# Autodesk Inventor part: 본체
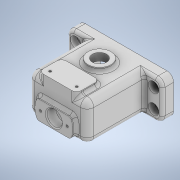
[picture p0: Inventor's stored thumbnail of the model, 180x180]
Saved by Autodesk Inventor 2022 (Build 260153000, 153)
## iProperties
Created: 2023-12
Part Number: 본체
Material: 일반
Document SubType Name: Modeling
Designer: PC-01
Density: 1 g/cm^3
Appearance: 기본값
Author: PC-01
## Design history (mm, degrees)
sketch "스케치1"
  geometry: L1 (-70, 0)-(70, 0) reference; L2 (0, -33.6)-(0, 33.6) reference; L3 (-50, 24)-(50, 24); L4 (50, 24)-(50, -24); L5 (50, -24)-(-50, -24); L6 (-50, -24)-(-50, 24); 1 further point
  constraints: 8 end point, 2 perpendicular, 1 horizontal, 2 other
  dimensions: "d0" = 100 distance of L3.start L3.end; "d1" = 48 distance of L3.end L4.end
extrude "돌출1" new body sketch "스케치1" stored distance "d2" = 76; taper "d3" = 0 deg
sketch "스케치2"
  geometry: L1 (50, -38)-(50, 38) reference; L2 (50, -26)-(31, -26); L3 (31, -26)-(31, 38); L4 (-50, 38)-(50, 38) reference; L5 (-31, 38)-(-31, -26); L6 (-31, -26)-(-50, -26); L7 (-50, -38)-(-50, 38) reference; L8 (31, 38)-(-31, 38); L9 (0, -53.2)-(0, 53.2) reference; L10 (70, 0)-(-70, 0) reference; L11 (50, -38)-(-50, -38) reference; L12 (50, -26)-(50, -38); L13 (50, -38)-(-50, -38); L14 (-50, -38)-(-50, -26); L15 (50, 38)-(50, -26); L16 (50, 38)-(31, 38); L17 (-31, 38)-(-50, 38); L18 (-50, 38)-(-50, -26); 2 further points
  constraints: 24 end point, 5 collinear, 5 perpendicular, 5 point on line, 1 vertical, 2 other
  dimensions: "d4" = 62 distance between parallel lines of L5 L3; "d5" = 12 distance between parallel lines of L11 L2
extrude "돌출2" cut sketch "스케치2" stored distance "d6" = 76; taper "d7" = 0 deg
sketch "스케치3"
  geometry: L1 (64, 0)-(0, 0) reference; L2 (76, 0)-(64, 0) reference; L3 (0, 0)-(76, 0); L4 (76, 0)-(76, 4); L5 (76, 48)-(76, 0) reference; L6 (0, 0)-(0, 48) reference; L7 (0, 0)-(0, 4); L8 (76, 4)-(0, 4); L9 (0, 48)-(64, 48) reference; L10 (0, 48)-(76, 48); L11 (76, 48)-(76, 44); L12 (76, 44)-(0, 44); L13 (0, 44)-(0, 48); 4 further points
  constraints: 16 end point, 3 point on line, 2 parallel, 2 perpendicular, 1 collinear, 1 horizontal
  dimensions: "d8" = 4 distance between parallel lines of L1 L8; "d9" = 4 distance between parallel lines of L9 L12
extrude "돌출3" cut sketch "스케치3" stored distance "d10" = 500; taper "d11" = 0 deg
sketch "스케치4"
  geometry: L1 (19, -12)-(-81, -12) reference; L2 (19, 0)-(19, -12) reference; C1 r 20 at (-31, 16); 1 further point
  constraints: 1 centre point
  dimensions: "d12" = 40 diameter of C1; "d13" = 28 distance from line of L1 C1.centre; "d14" = 50 distance from line of L2 C1.centre
extrude "돌출4" join sketch "스케치4" distance "d15" = 4; taper "d16" = 0 deg
sketch "스케치5"
  geometry: L1 (64, 0)-(0, 0) reference; L2 (64, 40)-(0, 40) reference; L3 (0, 0)-(4, 0); L4 (4, 0)-(4, 40); L5 (4, 40)-(0, 40); L6 (0, 40)-(0, 0); 3 further points
  constraints: 8 end point, 2 parallel, 1 horizontal, 1 perpendicular, 1 point on line
  dimensions: "d17" = 4 distance between parallel lines of L6 L4
extrude "돌출5" cut sketch "스케치5" stored distance "d18" = 500; taper "d19" = 0 deg
sketch "스케치6"
  geometry: L1 (19, -72)-(81, -72) reference; L2 (70, -72)-(30, -72); L3 (30, -72)-(30, -48); L4 (30, -48)-(70, -48); L5 (70, -48)-(70, -72); L6 (19, -72)-(19, -12) reference; L7 (0, 0)-(100, 0) reference; L8 (100, 0)-(100, -12) reference; C1 r 12 at (50, -28); 2 further points
  constraints: 8 end point, 2 parallel, 1 centre point, 1 horizontal, 1 perpendicular, 1 point on line
  dimensions: "d20" = 24 distance of L4.end L2.start; "d21" = 40 distance of L3.end L4.end; "d22" = 11 distance between parallel lines of L6 L3; "d23" = 24 diameter of C1; "d24" = 28 distance from line of L7 C1.centre; "d25" = 50 distance from line of L8 C1.centre
extrude "돌출6" join sketch "스케치6" distance "d26" = 4; taper "d27" = 0 deg
sketch "스케치8"
  geometry: L1 (50, -28)-(-50, -28) reference; C1 r 9 at (0, 0); 1 further point
  constraints: 1 centre point
  dimensions: "d30" = 18 diameter of C1; "d31" = 28 distance from line of L1 C1.centre; "d32" = 10 distance of point (0, 10) C1.centre
extrude "돌출7" cut sketch "스케치8" distance "d33" = 8; taper "d34" = 0 deg
sketch "스케치10"
  geometry: C1 r 12 at (0, 0) reference; 2 further points
  constraints: 1 coincident
hole "구멍1" sketch "스케치10" at (0, 0) diameter "d35" = 14.91747; stored, may be unused: countersink angle "d39" = 90 deg, drill point angle "d41" = 0 deg; dims "d36" = 8, "d37" = 4, "d38" = 2, "d40" = 0.998
sketch "스케치12"
  geometry: L1 (27, -16)-(-27, -16); L2 (-27, -16)-(-27, 16); L3 (-27, 16)-(27, 16); L4 (27, 16)-(27, -16); L5 (70, 0)-(-70, 0) reference; L6 (0, -33.6)-(0, 33.6) reference; L7 (-50, -20)-(50, -20) reference; L8 (-31, -20)-(-31, 20) reference; 1 further point
  constraints: 8 end point, 2 parallel, 1 horizontal, 1 perpendicular, 2 other
  dimensions: "d42" = 4 distance between parallel lines of L1 L7; "d43" = 4 distance between parallel lines of L8 L2
extrude "돌출8" cut sketch "스케치12" distance "d44" = 66; taper "d45" = 0 deg
sketch "스케치13"
  geometry: L1 (50, -28)-(-50, -28) reference; L2 (50, -16)-(50, -28) reference; L3 (31, 44)-(31, -16) reference; L4 (-31, -16)-(-31, 44) reference; A1 r 15 centre (0, 0) between (0, 15) and (-15, 0); 3 further points
  constraints: 4 point on circle, 1 centre point
  dimensions: "d46" = 30 diameter of A1; "d47" = 28 distance from line of L1 A1.centre; "d48" = 50 distance from line of L2 A1.centre; "d49" = 31 distance from line of L3 A1.start; "d50" = 16 distance from line of L4 A1.end; "d51" = 16 distance from line of L3 point (15, 0); "d52" = 13 distance from line of L1 point (0, -15)
hole "구멍2" sketch "스케치13" at (0, 15), (-15, 0), (0, -15), (15, 0) diameter "d53" = 2.459; stored, may be unused: countersink angle "d57" = 90 deg, drill point angle "d59" = 0 deg; dims "d54" = 6, "d55" = 4, "d56" = 2, "d58" = 8.8
sketch "스케치14"
  geometry: L1 (30, -48)-(30, -72) reference; L2 (70, -72)-(70, -48) reference; L3 (30, -72)-(70, -72) reference; 3 further points
  dimensions: "d60" = 28 distance of point (36, -66) point (64, -66); "d61" = 6 distance from line of L1 point (36, -66); "d62" = 6 distance from line of L2 point (64, -66); "d63" = 6 distance from line of L3 point (64, -66)
hole "구멍3" sketch "스케치14" at (64, -66), (36, -66) diameter "d64" = 2.459; stored, may be unused: countersink angle "d68" = 90 deg, drill point angle "d70" = 0 deg; dims "d65" = 8, "d66" = 4, "d67" = 2, "d69" = 8.8
sketch "스케치15"
  geometry: L1 (100, 0)-(81, 0) reference; L2 (81, -40)-(100, -40) reference; L3 (100, 0)-(100, -40) reference; L4 (0, -40)-(0, 0) reference; 5 further points
  dimensions: "d71" = 20 distance of point (91, -10) point (91, -30); "d72" = 20 distance of point (9, -10) point (9, -30); "d73" = 82 distance of point (9, -30) point (91, -30); "d74" = 82 distance of point (9, -10) point (91, -10); "d75" = 10 distance from line of L1 point (91, -10); "d76" = 10 distance from line of L2 point (91, -30); "d77" = 9 distance from line of L3 point (91, -30); "d78" = 9 distance from line of L4 point (9, -30)
hole "구멍4" sketch "스케치15" at (91, -30), (91, -10), (9, -30), (9, -10) diameter "d79" = 6.756; stored, may be unused: countersink angle "d83" = 82 deg, drill point angle "d85" = 0 deg; dims "d80" = 8, "d81" = 11, "d82" = 6.6, "d84" = 12
sketch "스케치16"
  geometry: L1 (28, 44)-(4, 44) reference; L2 (-12, 0)-(-12, 40) reference; 2 further points
  constraints: 1 other
  dimensions: "d86" = 23 distance from line of L1 point (28, 21); "d87" = 40 distance from line of L2 point (28, 21)
feature "엠보싱1" sketch "스케치16" dims "d88" = 0.5, "d89" = 0
sketch "스케치17"
  geometry: L1 (-7.126, 23)-(-55.615, 23); L2 (-51, 44)-(-11, 44) reference; L3 (19, 40)-(19, 0) reference; L4 (0, 0)-(-62, 0) reference; L5 (-8.148, 3)-(-55.615, 3); L6 (-58, 36)-(-58, 4) reference; C1 r 20 at (-31, 13); 5 further points
  constraints: 4 end point, 1 centre point, 1 horizontal, 1 perpendicular
  dimensions: "d90" = 40 diameter of C1; "d91" = 31 distance from line of L2 C1.centre; "d92" = 50 distance from line of L3 C1.centre; "d95" = 10 distance from line of C1.centre L1; "d96" = 10 distance from line of L5 C1.centre
extrude "돌출9" join sketch "스케치17" distance "d97" = 4; taper "d98" = 0 deg
sketch "스케치18"
  geometry: L1 (-51, 44)-(-11, 44) reference; L2 (-81, 0)-(-81, 40) reference; C1 r 8 at (-31, 13); 1 further point
  constraints: 1 centre point
  dimensions: "d99" = 16 diameter of C1; "d100" = 31 distance from line of L1 C1.centre; "d101" = 50 distance from line of L2 C1.centre
extrude "돌출10" cut sketch "스케치18" distance "d102" = 20; taper "d103" = 0 deg
sketch "스케치19"
  geometry: L1 (19, 40)-(19, 0) reference; L2 (-81, 0)-(-81, 40) reference; L3 (-51, 44)-(-11, 44) reference; 3 further points
  dimensions: "d104" = 28 distance of point (-45, 13) point (-17, 13); "d105" = 36 distance from line of point (-17, 13) L1; "d106" = 36 distance from line of L2 point (-45, 13); "d107" = 31 distance from line of L3 point (-45, 13)
hole "구멍5" sketch "스케치19" at (-17, 13), (-45, 13) diameter "d108" = 2.459; stored, may be unused: countersink angle "d112" = 90 deg, drill point angle "d114" = 0 deg; dims "d109" = 10, "d110" = 4, "d111" = 2, "d113" = 8
fillet "모깎기1" dims "d115" = 7
fillet "모깎기2" dims "d116" = 7
chamfer "모따기1" distance "d117" = 1; stored, may be unused: second distance "d118" = 2, angle "d119" = 45 deg
fillet "모깎기3" dims "d120" = 5
fillet "모깎기4" dims "d121" = 7
fillet "모깎기5" dims "d122" = 3
fillet "모깎기6" dims "d123" = 3
node "솔리드1"
feature "A9D066F2-1C7D-4E18-AEED-F7BC21143FA4" dims "d35" = 14.91747, "d36" = 8, "d37" = 4, "d38" = 2, "d39" = 90 deg, "d40" = 0.998, "d41" = 0
